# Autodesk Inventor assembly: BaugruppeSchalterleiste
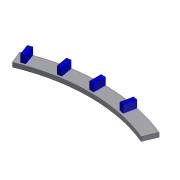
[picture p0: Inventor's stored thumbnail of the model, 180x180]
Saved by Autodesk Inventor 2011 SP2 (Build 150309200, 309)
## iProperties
Created: 2012-07
Part Number: BaugruppeSchalterleiste
Document SubType Name: Assembly
Designer: Thomas Kötschau
Author: Thomas Kötschau
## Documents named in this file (3)
- C:\Users\martin\Desktop\loeschenn\orgel\BaugruppeSchalterleiste\BaugruppeSchalterleiste.iam
- C:\Users\martin\Desktop\loeschenn\orgel\BaugruppeSchalterleiste\Murks1_Leiste.ipt
- C:\Users\martin\Desktop\loeschenn\orgel\BaugruppeSchalterleiste\Murks1_Schalter.ipt
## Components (5 placed, 2 different names)
1. Leiste:1 — Passend:1, Fluchtend:1, Fluchtend:2, Passend:3, Passend:5, Winkel:1, Passend:6
2. Schalter:2 — Passend:3, Passend:5, Winkel:1, Passend:6
3. Schalter:1 — Passend:1, Fluchtend:1, Fluchtend:2
4. Schalter:3
5. Schalter:4
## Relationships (7: Mate 4, Flush 2, Angle 1)
- Passend:1 [Mate]: Leiste:1 ↔ Schalter:1
- Fluchtend:1 [Flush]: Leiste:1 ↔ Schalter:1
- Fluchtend:2 [Flush]: Leiste:1 ↔ Schalter:1
- Passend:3 [Mate]: Leiste:1 ↔ Schalter:2
- Passend:5 [Mate]: Leiste:1 ↔ Schalter:2
- Winkel:1 [Angle]: Leiste:1 ↔ Schalter:2
- Passend:6 [Mate]: Leiste:1 ↔ Schalter:2
